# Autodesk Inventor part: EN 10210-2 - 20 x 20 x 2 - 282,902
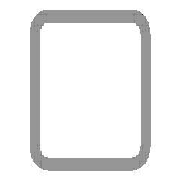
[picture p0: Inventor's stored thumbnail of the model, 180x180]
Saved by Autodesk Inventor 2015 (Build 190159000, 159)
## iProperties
_CCFamilyMember: 1
_CCFamilyDisplayName: DIN EN 10210-2 (Square) - Tube
_FrameMemberDoc: Frame Member File
_Version: 15.0.0
_GetPNFromCC: 1
Created: 2015-05
Part Number: EN 10210-2 - 20 x 20 x 2 - 282,902
Material: Steel, Mild
Description: Tube
Document SubType Name: Modeling
Standard: DIN
Designer: TREINA6
Standard Revision: 1997
Standards Organization: DIN
Language: en-US
Size Designation: 20 x 20 x 2
Categories: <MemberInstance><Categories><Category DisplayName="Structural Shapes" InternalName="089c4875-fa83-4c05-b084-43b9cc11f5ed" Mnemonic="GRDR"><CategoryParameter Dis
Stock Number: 20 x 20 x 2
Density: 7.85 g/cm^3
Appearance: Semi-Polished
IsCustomPart: 1
G_L: 282,902 mm
G_W: 20,000 mm
G_H: 20,000 mm
+E0A39B40-F93E-43A3-86F3-37080D4D8280+CUTDETAIL1: Miter 60,00 deg
+AF65A11D-AA21-4BB6-9A7F-682C94FE4538+CUTDETAIL2: Miter 60,00 deg
Author: TREINA6
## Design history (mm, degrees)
node "Start plane"
node "End plane"
sketch "Sketch"
  geometry: L1 (-10, -7)-(-10, 7); L2 (-7, 10)-(7, 10); L3 (10, 7)-(10, -7); L4 (7, -10)-(-7, -10); L5 (-7, 8)-(7, 8); L6 (8, 7)-(8, -7); L7 (7, -8)-(-7, -8); L8 (-8, -7)-(-8, 7); L9 (0, 14.87)-(0, -14.87) reference; L10 (-14.87, 0)-(14.87, 0) reference; A1 r 3 centre (-7, -7) between (-10, -7) and (-7, -10); A2 r 3 centre (-7, 7) between (-7, 10) and (-10, 7); A3 r 3 centre (7, 7) between (10, 7) and (7, 10); A4 r 3 centre (7, -7) between (7, -10) and (10, -7); A5 r 1 centre (-7, 7) between (-7, 8) and (-8, 7); A6 r 1 centre (7, 7) between (8, 7) and (7, 8); A7 r 1 centre (7, -7) between (7, -8) and (8, -7); A8 r 1 centre (-7, -7) between (-8, -7) and (-7, -8)
  constraints: 16 end point, 16 point on circle, 8 centre point, 8 tangent, 4 parallel, 3 equal radius, 2 perpendicular, 7 other
  dimensions: "d7" = 3 radius of A1 (= G_IR); "d10" = 20 distance between parallel lines of L2 L4 (= G_H); "d11" = 20 distance between parallel lines of L1 L3 (= G_W); "d12" = 2 distance between parallel lines of L3 L6 (= G_T); "d15" = 10 distance between parallel lines of L2 L10 (= 0.5 x d10); "d16" = 10 distance between parallel lines of L9 L3 (= 0.5 x d11)
extrude "Body" new body sketch "Sketch" stored distance "d3" = 282.90163 (= G_L); taper "d4" = 0 deg
node "Driven Length"
  sketch "Sketch3"
    geometry: L1 (0, 0)-(10, 0) reference
    constraints: 2 end point, 1 horizontal
  workplane "Work Plane3"
  sketch "Sketch4"
    geometry: L1 (-2, 0)-(12, 0) reference; L2 (-2, 282.902)-(12, 282.902) reference
    dimensions: "d18" = 282.90163 distance between parallel lines of L1 L2 (derived)
workplane "Work Plane4"
split "Split1"
workplane "Work Plane5"
split "Split2"
body "Solid1"
other parameters: "G_W" = 20 [user parameter; used in 1 equation term], "G_H" = 20 [user parameter; used in 1 equation term], "G_T" = 2 [user parameter; used in 1 equation term], "G_IR" = 3 [user parameter; used in 1 equation term], "G_L" = 282.90163 (= d18) [user parameter; used in 1 equation term], "G_OFFSET_START" = 0 [user parameter; used in 1 equation term], "G_OFFSET_END" = 0 [user parameter; used in 1 equation term], "d13" = 0 (computed from G_OFFSET_START), "d14" = 282.90163 (= G_OFFSET_END + B_L), "B_L" = 282.90163 [user parameter; used in 1 equation term], "d17" = 90 deg
